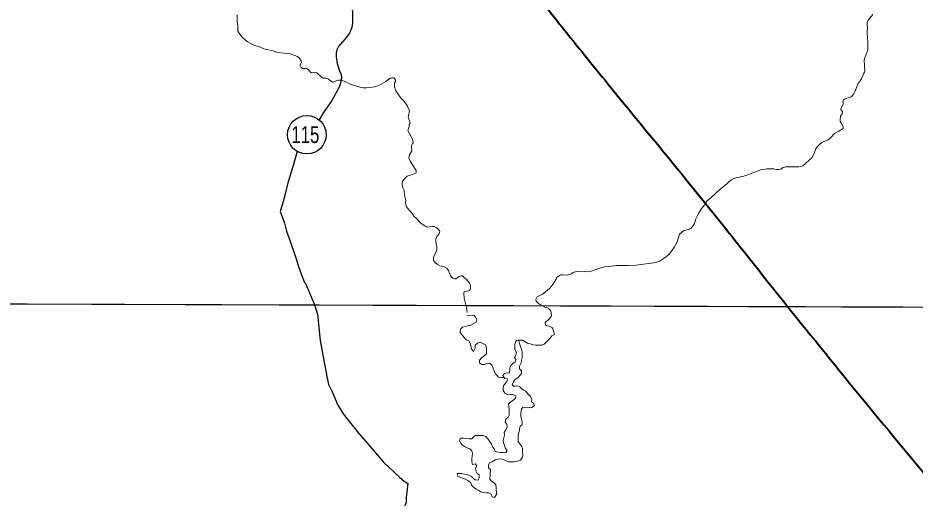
# Model space of a CAD drawing. Extents: x 553962 to 842807, y 8883888 to 9032388.
# Drawn here: x 614032 to 617774, y 8909058 to 8911062 of the extents above; entities that cross this region are included whole.
import ezdxf
from ezdxf.enums import TextEntityAlignment as Align

# ---------------------------------------------------------------- set-up
doc = ezdxf.new("R2010")
doc.units = 0
doc.header["$LTSCALE"] = 200
doc.layers.add('6', color=7, linetype='Continuous', lineweight=13)

msp = doc.modelspace()

# ---------------------------------------------------------------- linework, layer by layer
at = {"layer": '6', "lineweight": 25}
msp.add_line((615138.8, 8910295.4), (615126.6, 8910258.3), dxfattribs=at)
at = {"layer": '6'}
for p, q in [((574653.9, 8910009.3), (626625.7, 8909822.1)), ((615904.1, 8909819.7), (615934.2, 8909820.7)), ((615934.2, 8909820.7), (615904.1, 8909819.7))]:
    msp.add_line(p, q, dxfattribs=at)
at = {"layer": '6', "lineweight": 25}
for points in [[(615426.4, 8911122.4), (615426.8, 8911058.8), (615427.6, 8911043.4), (615425.9, 8911028), (615422.1, 8911015), (615414.6, 8910998.4), (615403.9, 8910983.4), (615369.6, 8910943.1), (615362.5, 8910929), (615358.7, 8910915.2), (615358.7, 8910898.9), (615363.5, 8910871.4), (615371.8, 8910845.5), (615378.5, 8910828.5), (615382, 8910815.5), (615381.8, 8910809.8), (615377.1, 8910788.9), (615371.3, 8910773.5), (615341.2, 8910717.8), (615307.1, 8910666.5), (615288.4, 8910636.1)], [(615196.8, 8910504.9), (615177.9, 8910436.4), (615158.9, 8910377.1), (615138.8, 8910295.4)], [(615126.6, 8910258.3), (615125.9, 8910253.6), (615134.7, 8910231.8), (615144, 8910204.7), (615152.8, 8910172.4), (615162.3, 8910145.7), (615166.8, 8910130.4), (615195.1, 8910047.8), (615199.5, 8910032.8), (615209.6, 8910005.2)], [(615209.6, 8910005.2), (615227, 8909957.6), (615232.7, 8909951.5), (615237, 8909940.3), (615244.4, 8909924.9), (615267.1, 8909868.1), (615282, 8909824.9)], [(615282, 8909824.9), (615292.5, 8909716.1), (615320.5, 8909565.2), (615327.5, 8909531.6), (615344.7, 8909497.9), (615365.9, 8909445.9), (615390.2, 8909408.2), (615414.6, 8909376.6), (615454.1, 8909327.6), (615483.5, 8909293.9), (615556.6, 8909207.2), (615624.7, 8909143.6), (615643.3, 8909127.9), (615658.6, 8909118.9)], [(615658.6, 8909118.9), (615650.8, 8909060.3), (615650.7, 8909038.9), (615643.5, 8909018.5), (615634.3, 8909007.3), (615618.9, 8908978.8), (615603.5, 8908958.5), (615594.3, 8908950.4), (615582.5, 8908946.1), (615559.6, 8908945.5)]]:
    msp.add_lwpolyline(points, dxfattribs=at)
at = {"layer": '6'}
for points in [[(614946.1, 8911074.3), (614946.5, 8911046), (614948.7, 8911031.5), (614949.6, 8911006.3), (614960.5, 8910989.7), (614969.6, 8910979.2), (614979.4, 8910970.7), (614988.7, 8910963.9), (615010.6, 8910951.4), (615020.6, 8910946.9), (615040, 8910940.5), (615058, 8910932.4), (615068.1, 8910929.7), (615094.7, 8910924.8), (615114.8, 8910917.8), (615166.8, 8910911.8), (615187.2, 8910905), (615197.9, 8910900.2), (615206.5, 8910893.3), (615213.6, 8910883.4), (615215, 8910876), (615209.8, 8910865.4), (615209.1, 8910862.7), (615213.4, 8910855.6), (615220.2, 8910850.1), (615223.2, 8910849.3), (615226.8, 8910849.7), (615230.9, 8910851.5), (615235.7, 8910851.1), (615242.4, 8910846.7), (615250.7, 8910837.1), (615255.1, 8910833.3), (615267.9, 8910833.6), (615278.9, 8910832), (615282.1, 8910830.2)], [(614946.1, 8911074.3), (614946.5, 8911046), (614948.7, 8911031.5), (614949.6, 8911006.3), (614960.5, 8910989.7), (614969.6, 8910979.2), (614979.4, 8910970.7), (614988.7, 8910963.9), (615010.6, 8910951.4), (615020.6, 8910946.9), (615040, 8910940.5), (615058, 8910932.4), (615068.1, 8910929.7), (615094.7, 8910924.8), (615114.8, 8910917.8), (615166.8, 8910911.8), (615187.2, 8910905), (615197.9, 8910900.2), (615206.5, 8910893.3), (615213.6, 8910883.4), (615215, 8910876), (615209.8, 8910865.4), (615209.1, 8910862.7), (615213.4, 8910855.6), (615220.2, 8910850.1), (615223.2, 8910849.3), (615226.8, 8910849.7), (615230.9, 8910851.5), (615235.7, 8910851.1), (615242.4, 8910846.7), (615250.7, 8910837.1), (615255.1, 8910833.3), (615267.9, 8910833.6), (615278.9, 8910832), (615282.1, 8910830.2)], [(617562.8, 8910835.9), (617564, 8910837.8), (617562.3, 8910886.7), (617564.9, 8910895.9), (617573, 8910917.7), (617576.3, 8910929), (617577.6, 8910937.7), (617576.3, 8910959.7), (617576, 8910981.6), (617574.1, 8910994.8), (617574.2, 8911006.4), (617575.1, 8911016.5), (617573.7, 8911034.4), (617574.5, 8911043.2), (617578.9, 8911051.8), (617598.1, 8911076.2)], [(615282.1, 8910830.2), (615283.3, 8910828.4), (615301.8, 8910812), (615305.6, 8910810.9), (615317.4, 8910809.9), (615327, 8910806.2), (615334.1, 8910800.2), (615345.7, 8910794.2), (615350.8, 8910794.5), (615359.4, 8910799.7), (615362.8, 8910800.9), (615370.9, 8910802.2), (615381.1, 8910801.7), (615392.8, 8910798.4), (615422.1, 8910783.9), (615463.6, 8910771.7), (615471.6, 8910770.6), (615485.6, 8910770.5), (615518.7, 8910774.5), (615528.2, 8910776.4), (615537.8, 8910779.3), (615566.4, 8910796.3), (615584.6, 8910810.5), (615590.8, 8910812.2), (615600.7, 8910811.2), (615603.2, 8910808.9), (615606.8, 8910802), (615606.7, 8910796.5), (615602.9, 8910789.8), (615602.2, 8910786.7), (615603.2, 8910774.1), (615607.3, 8910759.9), (615613.3, 8910748.7), (615621.7, 8910736.7), (615632.2, 8910724.8), (615640.6, 8910717.5), (615655, 8910696.9)], [(615282.1, 8910830.2), (615283.3, 8910828.4), (615301.8, 8910812), (615305.6, 8910810.9), (615317.4, 8910809.9), (615327, 8910806.2), (615334.1, 8910800.2), (615345.7, 8910794.2), (615350.8, 8910794.5), (615359.4, 8910799.7), (615362.8, 8910800.9), (615370.9, 8910802.2), (615381.1, 8910801.7), (615392.8, 8910798.4), (615422.1, 8910783.9), (615463.6, 8910771.7), (615471.6, 8910770.6), (615485.6, 8910770.5), (615518.7, 8910774.5), (615528.2, 8910776.4), (615537.8, 8910779.3), (615566.4, 8910796.3), (615584.6, 8910810.5), (615590.8, 8910812.2), (615600.7, 8910811.2), (615603.2, 8910808.9), (615606.8, 8910802), (615606.7, 8910796.5), (615602.9, 8910789.8), (615602.2, 8910786.7), (615603.2, 8910774.1), (615607.3, 8910759.9), (615613.3, 8910748.7), (615621.7, 8910736.7), (615632.2, 8910724.8), (615640.6, 8910717.5), (615655, 8910696.9)], [(617500.8, 8910729.2), (617509.3, 8910733.5), (617512.1, 8910736.2), (617517.9, 8910744.5), (617522.7, 8910753.9), (617535.9, 8910785.2), (617550.5, 8910807.1), (617560.2, 8910831.5), (617562.8, 8910835.9)], [(615655, 8910696.9), (615656, 8910695), (615665, 8910674.5), (615660.6, 8910655.1), (615659.8, 8910646.5), (615660.9, 8910642.9), (615664.4, 8910636.8), (615668, 8910623.7), (615667.6, 8910622), (615664, 8910616.7), (615663.2, 8910608.5), (615658, 8910591.3), (615674.8, 8910560.7), (615678.6, 8910550.5), (615680.5, 8910541.2), (615679.6, 8910538.6), (615673.4, 8910528.9), (615673.3, 8910520.8), (615674.8, 8910510.7), (615674.5, 8910507.1), (615665.9, 8910491.1), (615662.8, 8910478.6), (615664, 8910473.1), (615667.5, 8910464.5), (615692.6, 8910424.9), (615693.7, 8910422.2), (615692.8, 8910415.3), (615690.4, 8910413.3), (615677.6, 8910408), (615667.7, 8910405.9), (615654.9, 8910400.8), (615643.2, 8910389.5), (615638, 8910382.3), (615634.6, 8910373.3), (615634, 8910366.5), (615637.8, 8910353.2), (615642.9, 8910341.4), (615643.7, 8910321.8), (615647.4, 8910310.9), (615649.7, 8910301.3), (615648.6, 8910289.1), (615649.3, 8910280.6), (615652.9, 8910273.4), (615657.9, 8910266.5), (615678, 8910244), (615684.8, 8910233.2), (615691.8, 8910227.6), (615712.5, 8910205.7), (615726.4, 8910195.1), (615735.1, 8910190.5), (615740.5, 8910189), (615748.6, 8910189.6), (615760.2, 8910191.7), (615768.2, 8910191.4), (615779.6, 8910185.2), (615787.6, 8910178.1), (615790.3, 8910174.6), (615791.2, 8910169.9), (615790.2, 8910166.1), (615787, 8910159.5), (615778.9, 8910148.9), (615775.1, 8910139), (615775.4, 8910128.9), (615779, 8910106.3), (615779.6, 8910095.5)], [(615655, 8910696.9), (615656, 8910695), (615665, 8910674.5), (615660.6, 8910655.1), (615659.8, 8910646.5), (615660.9, 8910642.9), (615664.4, 8910636.8), (615668, 8910623.7), (615667.6, 8910622), (615664, 8910616.7), (615663.2, 8910608.5), (615658, 8910591.3), (615674.8, 8910560.7), (615678.6, 8910550.5), (615680.5, 8910541.2), (615679.6, 8910538.6), (615673.4, 8910528.9), (615673.3, 8910520.8), (615674.8, 8910510.7), (615674.5, 8910507.1), (615665.9, 8910491.1), (615662.8, 8910478.6), (615664, 8910473.1), (615667.5, 8910464.5), (615692.6, 8910424.9), (615693.7, 8910422.2), (615692.8, 8910415.3), (615690.4, 8910413.3), (615677.6, 8910408), (615667.7, 8910405.9), (615654.9, 8910400.8), (615643.2, 8910389.5), (615638, 8910382.3), (615634.6, 8910373.3), (615634, 8910366.5), (615637.8, 8910353.2), (615642.9, 8910341.4), (615643.7, 8910321.8), (615647.4, 8910310.9), (615649.7, 8910301.3), (615648.6, 8910289.1), (615649.3, 8910280.6), (615652.9, 8910273.4), (615657.9, 8910266.5), (615678, 8910244), (615684.8, 8910233.2), (615691.8, 8910227.6), (615712.5, 8910205.7), (615726.4, 8910195.1), (615735.1, 8910190.5), (615740.5, 8910189), (615748.6, 8910189.6), (615760.2, 8910191.7), (615768.2, 8910191.4), (615779.6, 8910185.2), (615787.6, 8910178.1), (615790.3, 8910174.6), (615791.2, 8910169.9), (615790.2, 8910166.1), (615787, 8910159.5), (615778.9, 8910148.9), (615775.1, 8910139), (615775.4, 8910128.9), (615779, 8910106.3), (615779.6, 8910095.5)], [(617299.1, 8910441.8), (617305.3, 8910443.9), (617317.2, 8910453.6), (617331.8, 8910468.8), (617342.9, 8910478.3), (617351.6, 8910492.9), (617360.4, 8910515.6), (617367.5, 8910525), (617376.7, 8910534.6), (617384.6, 8910541.5), (617393.3, 8910546.7), (617411.8, 8910552.7), (617422, 8910562.3), (617437.5, 8910579.4), (617456.6, 8910589.1), (617473.9, 8910600.3), (617474.5, 8910603.6), (617473.9, 8910607.4), (617468.9, 8910619.3), (617461.8, 8910629.7), (617461.1, 8910638.3), (617462.7, 8910651.2), (617470.4, 8910661.1), (617471.7, 8910664.2), (617471.9, 8910668), (617471.1, 8910670.9), (617465, 8910679.6), (617464.6, 8910681.5), (617468, 8910692.2), (617473.8, 8910701.9), (617473.8, 8910707), (617472.5, 8910711.1), (617473.6, 8910717.2), (617475.2, 8910719.9), (617479.9, 8910723.1), (617489.2, 8910726.7), (617500.8, 8910729.2)], [(616192.8, 8909887.3), (616193.2, 8909889.8), (616197.7, 8909897.2), (616219.6, 8909908.3), (616226.1, 8909912.5), (616249, 8909932.6), (616257.3, 8909941.8), (616264.1, 8909951.3), (616276.8, 8909971.7), (616279.8, 8909979), (616287.1, 8909983.6), (616293.1, 8909988.7), (616295.8, 8909989.5), (616304.5, 8909990.1), (616324.8, 8909987.7), (616339.8, 8909993.6), (616350, 8910000.2), (616372.9, 8910004.4), (616415.3, 8910002.2), (616455.3, 8910015.7), (616467.7, 8910020.6), (616477.9, 8910023.4), (616496.8, 8910025), (616528.2, 8910029.2), (616577, 8910028.5), (616609.1, 8910030.1), (616684.8, 8910039.5), (616706, 8910045.3), (616736, 8910064.1), (616750.6, 8910079.1), (616770.5, 8910107.1), (616781.6, 8910127.4), (616791.2, 8910158.7), (616808.9, 8910174), (616828.5, 8910179.3), (616840.2, 8910184.9), (616847.3, 8910193.1), (616854.1, 8910204.5), (616859.9, 8910222.7), (616870.1, 8910245.9), (616883.5, 8910266.4), (616893.7, 8910279.4), (616901, 8910291.8), (616906.8, 8910298.1), (616923.7, 8910312.6), (616960.8, 8910347.6), (616987.3, 8910368.4), (616997.7, 8910378.3), (617007.8, 8910385.9), (617018, 8910391.8), (617026.7, 8910394.9), (617060.3, 8910401.7), (617077, 8910406.6), (617100.7, 8910417), (617130.8, 8910428.2), (617157.1, 8910431.9), (617184, 8910431.9), (617195.7, 8910429.2), (617206.4, 8910429.5), (617213.6, 8910431.1), (617223, 8910437.1), (617235.8, 8910440.2), (617289.8, 8910440.6), (617299.1, 8910441.8), (617299.1, 8910441.8)], [(615779.6, 8910095.5), (615777.8, 8910089), (615767.1, 8910068), (615765.5, 8910058.6), (615765.6, 8910051.5), (615766.8, 8910047.7), (615773.9, 8910038.9), (615776.6, 8910037.6), (615782, 8910032.8), (615792.4, 8910027.4), (615808.9, 8910024.1), (615821.1, 8910017.4), (615827.3, 8910008), (615836, 8909987.3), (615840.8, 8909979.7), (615845.5, 8909975.1), (615853.4, 8909973.2), (615858.7, 8909973.1)], [(615779.6, 8910095.5), (615777.8, 8910089), (615767.1, 8910068), (615765.5, 8910058.6), (615765.6, 8910051.5), (615766.8, 8910047.7), (615773.9, 8910038.9), (615776.6, 8910037.6), (615782, 8910032.8), (615792.4, 8910027.4), (615808.9, 8910024.1), (615821.1, 8910017.4), (615827.3, 8910008), (615836, 8909987.3), (615840.8, 8909979.7), (615845.5, 8909975.1), (615853.4, 8909973.2), (615858.7, 8909973.1)], [(615858.7, 8909973.1), (615872.3, 8909982.2), (615872.3, 8909982.2), (615880.5, 8909984.9), (615885.6, 8909985), (615890.5, 8909981.6), (615906.4, 8909966.9), (615915.9, 8909954.7), (615919.4, 8909943.5), (615920.1, 8909933.2), (615918.5, 8909928), (615915.6, 8909924.2), (615912.6, 8909922.4), (615895.5, 8909920.7), (615893.3, 8909918.3), (615891.8, 8909914.3), (615893.8, 8909891.8), (615903, 8909853.2), (615904.8, 8909843), (615905.3, 8909832)], [(615858.7, 8909973.1), (615872.3, 8909982.2), (615872.3, 8909982.2), (615880.5, 8909984.9), (615885.6, 8909985), (615890.5, 8909981.6), (615906.4, 8909966.9), (615915.9, 8909954.7), (615919.4, 8909943.5), (615920.1, 8909933.2), (615918.5, 8909928), (615915.6, 8909924.2), (615912.6, 8909922.4), (615895.5, 8909920.7), (615893.3, 8909918.3), (615891.8, 8909914.3), (615893.8, 8909891.8), (615903, 8909853.2), (615904.8, 8909843), (615905.3, 8909832)], [(616257, 8909818.6), (616254.6, 8909839.7), (616243.1, 8909850.2), (616229.2, 8909854.7), (616225.9, 8909857.9), (616206.9, 8909866.8), (616203.1, 8909869.8), (616194.2, 8909879.1), (616192.8, 8909887.3)], [(616064.9, 8909557.5), (616059.5, 8909560.9), (616049.3, 8909561), (616036.1, 8909562.1), (616029, 8909570.3), (616021.9, 8909578.4), (616017.9, 8909588.7), (616014, 8909599.9), (616010, 8909611.1), (616000.9, 8909620.3), (615989.7, 8909619.4), (615977.4, 8909615.4), (615967.3, 8909615.5), (615957.1, 8909622.7), (615957.2, 8909633.9), (615965.4, 8909643), (615975.6, 8909650.1), (615986.9, 8909660.2), (615987, 8909672.4), (615986.1, 8909685.6), (615982.1, 8909696.9), (615959.8, 8909708.2), (615948.6, 8909704.2), (615939.3, 8909696.1), (615939.2, 8909683.9), (615932, 8909669.7), (615924, 8909680.9), (615921, 8909694.2), (615918, 8909704.4), (615913, 8909713.6), (615902.9, 8909718.8), (615891.8, 8909729), (615881.7, 8909741.3), (615875.6, 8909750.5), (615878.8, 8909763.7), (615886, 8909771.8), (615897.2, 8909773.8), (615907.3, 8909776.8), (615921.6, 8909779.8), (615933.9, 8909786.8), (615943.1, 8909791.8), (615946.2, 8909803), (615940.1, 8909813.3), (615934.2, 8909820.7)], [(616269.4, 8909741.1), (616265.1, 8909760), (616263.7, 8909765.6), (616258.7, 8909770.3), (616248.6, 8909775.1), (616238.4, 8909776.8), (616232.9, 8909781), (616231.6, 8909791.2), (616236.2, 8909796.2), (616241.4, 8909799.2), (616246.6, 8909803.2), (616253.9, 8909813.2), (616257, 8909818.3), (616257, 8909818.6)], [(616116.8, 8909716.6), (616136.1, 8909717.2), (616157.4, 8909704.4), (616168.6, 8909701.2), (616181.8, 8909697.1), (616192.9, 8909696), (616204.1, 8909695.9), (616217.3, 8909695.9), (616227.5, 8909699.9), (616235.7, 8909709), (616243.9, 8909717.1), (616252.1, 8909725.2), (616259.3, 8909735.3), (616269.4, 8909741.1)], [(616120.8, 8909714.8), (616123.8, 8909702.5), (616127.8, 8909690.3), (616132.8, 8909679.1), (616135.7, 8909667.8), (616135.7, 8909657.6), (616135.6, 8909644.4), (616132.5, 8909633.2), (616130.3, 8909622), (616124.2, 8909608.8), (616124.1, 8909596.6), (616132.2, 8909589.4), (616132.1, 8909578.2), (616124.9, 8909569.1), (616116.7, 8909560), (616106.5, 8909552.9), (616099.3, 8909542.8), (616093.1, 8909530.6), (616102.2, 8909523.4), (616112.4, 8909526.4), (616124.6, 8909523.2), (616132.7, 8909515), (616140.8, 8909507.8), (616149.9, 8909503.7), (616158, 8909494.5), (616169.1, 8909483.2), (616175.1, 8909470.9), (616174, 8909459.8), (616182.1, 8909453.6), (616186.1, 8909444.4), (616175.8, 8909435.3), (616163.6, 8909434.3), (616149.4, 8909435.5), (616138.2, 8909436.6), (616132.1, 8909428.4), (616129.9, 8909414.2), (616129.8, 8909400.9), (616132.8, 8909387.7), (616134.8, 8909376.5), (616135.7, 8909364.2), (616127.5, 8909358.2), (616124.4, 8909346), (616123.3, 8909335.8), (616119.1, 8909322.6), (616119, 8909307.3), (616118.9, 8909293), (616126, 8909284.8), (616132, 8909276.6), (616137, 8909264.4), (616137, 8909253.2), (616137.9, 8909239.9), (616136.8, 8909228.7), (616127.6, 8909215.6), (616116.3, 8909211.5), (616101.1, 8909208.6), (616088.8, 8909208.7), (616078.7, 8909208.7), (616069.6, 8909213.9), (616060.4, 8909218), (616048.2, 8909221.2), (616037, 8909220.2), (616023.8, 8909217.2), (616009.5, 8909209.2), (615998.3, 8909205.2), (615995.2, 8909195), (615995.1, 8909183.8), (616003.2, 8909176.6), (616000.9, 8909136.9), (616006.9, 8909128.7), (616018.2, 8909122.1), (616024.8, 8909113.3), (616027, 8909100.1), (616027, 8909091.3), (616029.2, 8909075.9), (616022.6, 8909064.9), (616019.7, 8909060.4), (616009.5, 8909063.5), (616006.5, 8909073.7), (615996.4, 8909079.9), (615986.2, 8909079.9), (615973, 8909081), (615962.9, 8909084.2), (615953.8, 8909089.3), (615942.6, 8909095.5), (615931.5, 8909103.7), (615924.4, 8909111.9), (615920.4, 8909121.1), (615911.3, 8909130.3), (615897.1, 8909136.5), (615887, 8909140.7), (615875.8, 8909145.8), (615866.7, 8909150), (615863.7, 8909160.2), (615873.9, 8909160.1), (615884, 8909160.1), (615894.2, 8909158), (615904.4, 8909156.9), (615914.5, 8909152.7), (615923.6, 8909147.6), (615930.7, 8909140.4), (615939.8, 8909134.2)], [(615939.8, 8909134.2), (615952, 8909133.1), (615956.2, 8909144.3), (615955.2, 8909154.5), (615947.1, 8909160.7), (615942.1, 8909170.9), (615940.1, 8909182.1), (615946.3, 8909192.3), (615940.3, 8909200.4), (615928.1, 8909198.5), (615925.1, 8909208.7), (615925.2, 8909221.9), (615926.2, 8909232.1), (615928.4, 8909243.3), (615925.4, 8909255.6), (615916.3, 8909262.8), (615906.1, 8909266.9), (615895, 8909273.1), (615886.9, 8909279.2), (615879.8, 8909287.4), (615873.8, 8909298.7), (615877.9, 8909307.8), (615890.2, 8909307.7), (615903.4, 8909306.6), (615914.5, 8909304.5), (615924.7, 8909305.5), (615931.9, 8909312.6), (615939.1, 8909319.7), (615950.2, 8909319.6), (615961.4, 8909318.5), (615973.6, 8909318.4), (615983.8, 8909314.3), (615993.9, 8909304), (615999.9, 8909292.8), (616007, 8909282.5), (616012, 8909271.3), (616019, 8909263.1), (616023, 8909252.9), (616033.2, 8909249.8), (616045.4, 8909248.7), (616055.6, 8909248.6), (616065.7, 8909246.5), (616072.9, 8909255.6), (616063.8, 8909267.9), (616060.8, 8909278.1), (616056.8, 8909288.3), (616055.9, 8909299.6), (616058, 8909309.7), (616061.1, 8909319.9), (616060.2, 8909332.1), (616066.4, 8909343.3), (616072.6, 8909355.5), (616071.6, 8909365.7), (616064.6, 8909374.9), (616067.7, 8909387.1), (616076.9, 8909395.2), (616081, 8909404.3), (616081.1, 8909417.6), (616081.2, 8909427.8), (616079.2, 8909440), (616078.3, 8909451.2), (616089.6, 8909460.3), (616099.8, 8909467.4), (616107, 8909474.4), (616109.1, 8909484.6), (616096.9, 8909490.8), (616085.7, 8909489.9), (616075.5, 8909488.9), (616063.3, 8909496.1), (616055.3, 8909506.4), (616055.4, 8909516.6), (616057.5, 8909526.7), (616064.7, 8909535.8), (616071.8, 8909543.9), (616073.9, 8909555.1), (616061.8, 8909558.3), (616054.7, 8909569.5), (616060.9, 8909577.6), (616071.1, 8909580.6), (616081.2, 8909579.6), (616083.3, 8909591.8), (616083.4, 8909603), (616088.6, 8909613.1), (616096.8, 8909620.2), (616106, 8909626.2), (616109.1, 8909636.4), (616103, 8909644.6), (616108.2, 8909654.8), (616111.3, 8909665.9), (616104.3, 8909678.2), (616104.3, 8909688.4), (616104.4, 8909698.6), (616107.2, 8909708.9), (616111.2, 8909714.9), (616116.8, 8909716.6), (616120.8, 8909714.8)]]:
    msp.add_lwpolyline(points, dxfattribs=at)
msp.add_lwpolyline([(618535.2, 8909853.3), (607574.3, 8909890.7), (607543.3, 8898835.3), (618504.2, 8898795.8)], close=True, dxfattribs=at)
at = {"layer": '6', "lineweight": 25}
msp.add_circle((615237.1, 8910574.3), 80.3, dxfattribs=at)
at = {"layer": '6', "lineweight": 40}
msp.add_spline([(615971.7, 8911432.5), (616138.5, 8911227.2), (616313.3, 8911009), (616504.8, 8910771.9), (616895.5, 8910293.3), (617079.2, 8910062.8), (617725.5, 8909265.3), (618056.1, 8908857.7), (618263.2, 8908603.7), (618306.6, 8908556.9), (618336.6, 8908483.4), (618463.5, 8908212.8), (618533.7, 8908055.7), (618557.1, 8908012.3), (618590.5, 8907985.6), (618640.6, 8907962.2), (618764.1, 8907925.4), (618847.6, 8907882), (618877.7, 8907865.3), (618937.8, 8907811.8), (618997.9, 8907778.4), (619028, 8907745), (619141.5, 8907698.2), (619241.7, 8907674.8), (619372, 8907724.9), (619488.8, 8907801.8), (619552.3, 8907878.6), (619575.7, 8907905.4), (619599.1, 8907898.7), (619632.5, 8907871.9), (619679.2, 8907871.9), (619782.8, 8907918.7), (619872.9, 8907952.1), (619949.7, 8907952.1), (620026.6, 8907932.1), (620080, 8907908.7), (620120.1, 8907902), (620166.8, 8907932.1), (620233.6, 8907952.1), (620300.4, 8907958.8), (620363.9, 8907992.2), (620444, 8908052.4), (620517.5, 8908095.8), (620586.9, 8908115.3)], degree=3, dxfattribs=at)

# ---------------------------------------------------------------- texts
at = {"layer": '6', "width": 0.75}
msp.add_text('115', height=70, dxfattribs=at).set_placement((615230.8, 8910539.7), align=Align.CENTER)

doc.saveas('drawing.dxf')
